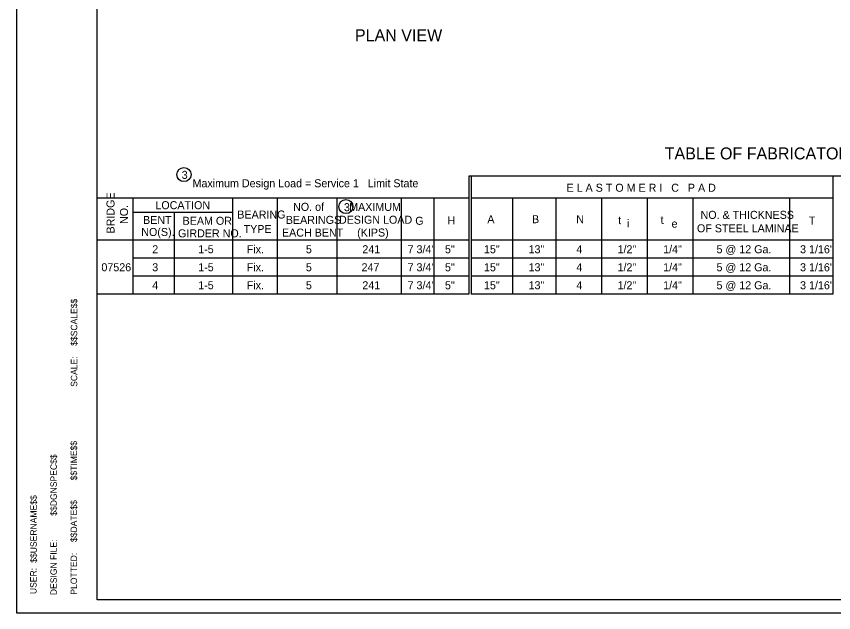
# Model space of a CAD drawing. Extents: x 32334 to 32601, y -901 to -733.
# Drawn here: x 32334.2 to 32436.3, y -900.6 to -826 of the extents above; entities that cross this region are included whole.
import ezdxf

# ---------------------------------------------------------------- set-up
doc = ezdxf.new("R2010")
doc.units = 0
for name, color, linetype in [('1', 7, 'Continuous'), ('CONC-PR$', 7, 'Continuous'), ('Level 1', 7, 'Continuous'), ('Level 63', 7, 'Continuous')]:
    doc.layers.add(name, color=color, linetype=linetype)

msp = doc.modelspace()

# ---------------------------------------------------------------- linework, layer by layer
at = {"layer": '1'}
for p, q in [((32390.71, -845.98), (32390.71, -848.72)), ((32442.28, -845.98), (32390.71, -845.98)), ((32391.01, -845.98), (32391.01, -848.72)), ((32436.18, -845.98), (32436.18, -848.72)), ((32361.22, -848.72), (32344.32, -848.72)), ((32348.77, -848.72), (32348.77, -860.75)), ((32361.22, -848.72), (32361.22, -860.75)), ((32361.22, -848.72), (32361.22, -860.75)), ((32390.71, -848.72), (32361.22, -848.72)), ((32366.77, -848.72), (32366.77, -860.75)), ((32374.22, -848.72), (32374.22, -860.75)), ((32382.28, -848.72), (32382.28, -860.75)), ((32386.35, -848.72), (32386.35, -860.75)), ((32390.71, -848.72), (32390.71, -860.75)), ((32418.98, -848.72), (32391.01, -848.72)), ((32391.01, -848.72), (32391.01, -860.75)), ((32396.17, -848.72), (32396.17, -860.75)), ((32401.58, -848.72), (32401.58, -860.75)), ((32401.58, -848.72), (32401.58, -860.75)), ((32407.28, -848.72), (32407.28, -860.75)), ((32412.98, -848.72), (32412.98, -860.75)), ((32418.69, -848.72), (32418.69, -860.75)), ((32436.18, -848.72), (32418.9, -848.72)), ((32430.78, -848.72), (32430.78, -860.75)), ((32436.18, -848.72), (32436.18, -860.75)), ((32361.22, -850.53), (32348.77, -850.53)), ((32353.93, -850.53), (32353.93, -860.75)), ((32348.54, -854), (32344.32, -854)), ((32361.22, -854), (32348.54, -854)), ((32390.71, -854), (32361.22, -854)), ((32430.68, -854), (32391.01, -854)), ((32436.18, -854), (32430.68, -854)), ((32361.22, -856.25), (32348.77, -856.25)), ((32390.71, -856.25), (32361.22, -856.25)), ((32430.68, -856.25), (32391.01, -856.25)), ((32436.18, -856.25), (32430.68, -856.25)), ((32361.22, -858.5), (32348.77, -858.5)), ((32390.71, -858.5), (32361.22, -858.5)), ((32430.68, -858.5), (32391.01, -858.5)), ((32436.18, -858.5), (32430.68, -858.5)), ((32361.22, -860.75), (32344.32, -860.75)), ((32390.71, -860.75), (32361.22, -860.75)), ((32430.68, -860.75), (32391.01, -860.75)), ((32436.18, -860.75), (32430.68, -860.75))]:
    msp.add_line(p, q, dxfattribs=at)
for centre in [(32355.14, -845.79), (32375.37, -849.79)]:
    msp.add_circle(centre, 0.88, dxfattribs=at)
at = {"layer": 'Level 1'}
for p, q in [((32344.3, -898.95), (32344.3, -734.59)), ((32597.25, -898.95), (32344.3, -898.95))]:
    msp.add_line(p, q, dxfattribs=at)
at = {"layer": 'Level 63'}
msp.add_lwpolyline([(32334.21, -900.55), (32600.85, -900.55), (32600.85, -732.97), (32334.21, -732.97)], close=True, dxfattribs=at)

# ---------------------------------------------------------------- texts
at = {"layer": '1'}
for s, height, p in [('PLAN VIEW', 1.498, (32376.49, -829.11)), ('TABLE OF FABRICATOR VARIABLES', 1.498, (32415.18, -843.89)), ('3', 1, (32354.86, -846.32)), ('Maximum Design Load = Service 1   Limit State', 1, (32356.21, -847.37)), ('E L A S T O M E R I   C   P A D', 1, (32402.92, -847.93)), ('LOCATION', 1, (32351.57, -850.11)), ('BEARING', 1, (32361.8, -851.28)), ('NO. of ', 1, (32368.77, -850.32)), ('3', 1, (32375.12, -850.36)), ('  MAXIMUM', 1, (32375.03, -850.33)), ('BENT', 1, (32350.03, -851.96)), ('BEAM OR', 1, (32354.97, -852.06)), ('BEARINGS', 1, (32367.86, -851.95)), ('DESIGN LOAD', 1, (32374.5, -851.93)), ('G', 1, (32384.03, -852.06)), ('H', 1, (32388.06, -852.02)), ('A', 1, (32393.03, -851.87)), ('B', 1, (32398.61, -851.86)), ('N', 1, (32404.13, -851.86)), ('t', 1, (32409.36, -851.98)), (' t ', 1, (32414.3, -851.95)), ('NO. & THICKNESS', 1, (32419.66, -851.32)), ('T', 1, (32433.18, -852.04)), ('TYPE', 1, (32362.59, -853.09)), ('i', 1, (32410.47, -852.39)), ('e', 1, (32416.04, -852.42)), ('OF STEEL LAMINAE', 1, (32419.21, -853)), ('NO(S).', 1, (32349.81, -853.46)), ('GIRDER NO.', 1, (32354.4, -853.63)), ('EACH BENT', 1, (32367.38, -853.54)), ('(KIPS)', 1, (32376.77, -853.53))]:
    msp.add_text(s, height=height, dxfattribs=at).set_placement(p)
for s, p in [('BRIDGE', (32346.47, -853.15)), ('NO.', (32348.15, -851.96))]:
    msp.add_text(s, height=1, rotation=90, dxfattribs=at).set_placement(p)
at = {"layer": 'CONC-PR$'}
for s, p in [('2', (32351.18, -855.62)), ('1-5', (32356.92, -855.62)), ('Fix.', (32362.98, -855.62)), ('5', (32370.37, -855.62)), ('241', (32377.42, -855.62)), ('7 3/4"', (32383.07, -855.62)), ('5"', (32387.74, -855.62)), ('15"', (32392.61, -855.62)), ('13"', (32398.18, -855.62)), ('4', (32404.15, -855.62)), ('1/2"', (32409.29, -855.62)), ('1/4"', (32414.99, -855.62)), ('5 @ 12 Ga.', (32421.65, -855.62)), ('3 1/16"', (32432.09, -855.62)), ('07526', (32344.83, -857.87)), ('3', (32351.18, -857.87)), ('1-5', (32356.92, -857.87)), ('Fix.', (32362.98, -857.87)), ('5', (32370.37, -857.87)), ('247', (32377.32, -857.87)), ('7 3/4"', (32383.07, -857.87)), ('5"', (32387.74, -857.87)), ('15"', (32392.61, -857.87)), ('13"', (32398.18, -857.87)), ('4', (32404.15, -857.87)), ('1/2"', (32409.29, -857.87)), ('1/4"', (32414.99, -857.87)), ('5 @ 12 Ga.', (32421.65, -857.87)), ('3 1/16"', (32432.09, -857.87)), ('4', (32351.18, -860.12)), ('1-5', (32356.92, -860.12)), ('Fix.', (32362.98, -860.12)), ('5', (32370.37, -860.12)), ('241', (32377.42, -860.12)), ('7 3/4"', (32383.07, -860.12)), ('5"', (32387.74, -860.12)), ('15"', (32392.61, -860.12)), ('13"', (32398.18, -860.12)), ('4', (32404.15, -860.12)), ('1/2"', (32409.29, -860.12)), ('1/4"', (32414.99, -860.12)), ('5 @ 12 Ga.', (32421.65, -860.12)), ('3 1/16"', (32432.09, -860.12))]:
    msp.add_text(s, height=1, dxfattribs=at).set_placement(p)
at = {"layer": 'Level 1'}
for s, p in [('$$SCALE$$', (32341.81, -867.19)), ('SCALE:', (32341.81, -872.32)), ('$$TIME$$', (32341.78, -884.01)), ('$$DGNSPEC$$', (32339.26, -888.43)), ('$$USERNAME$$', (32336.76, -894.31)), ('$$DATE$$', (32341.78, -891.72)), ('DESIGN FILE:', (32339.26, -898.36)), ('PLOTTED:', (32341.78, -898.3)), ('USER:', (32336.73, -898.23))]:
    msp.add_text(s, height=0.8, rotation=90, dxfattribs=at).set_placement(p)

doc.saveas('drawing.dxf')
